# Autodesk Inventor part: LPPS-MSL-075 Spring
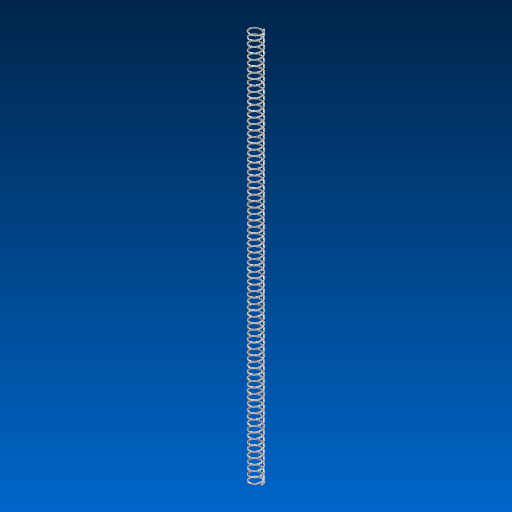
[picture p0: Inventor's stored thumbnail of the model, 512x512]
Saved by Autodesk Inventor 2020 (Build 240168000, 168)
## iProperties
Created: 2019-07
Part Number: LPPS-MSL-075 Spring
Material: Stainless Steel
Document SubType Name: Modeling
Designer: J. Nielson
Density: 8 g/cm^3
Appearance: Semi-Polished
Author: J. Nielson
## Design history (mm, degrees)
sketch "Sketch1"
  geometry: L1 (4, 49.746)-(-4, 49.746) reference; L2 (-2.5, 181.406)-(2.5, 181.406) reference; L3 (0, 181.406)-(0, 49.746); C1 r 0.178 at (1.905, 49.924); 1 further point
  constraints: 2 end point, 2 midpoint, 1 centre point, 1 tangent
  dimensions: "d0" = 0.3556 diameter of C1; "d1" = 1.905 distance from line of L3 C1.centre; "d2" = 131.6604 distance between parallel lines of L1 L2 (derived)
coil "Coil1" sketch "Sketch1" pitch "d3" = 25.4; turns "d5" = 70; dims "d4" = 131.3048 (= d2 - d0), "d6" = 0, angle "d7" = 30 deg, angle "d8" = 180 deg, "d9" = 30 deg, "d10" = 180 deg
body "Solid1"
node "Reference1"
node "Reference2"
